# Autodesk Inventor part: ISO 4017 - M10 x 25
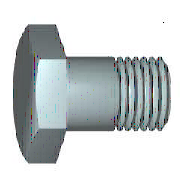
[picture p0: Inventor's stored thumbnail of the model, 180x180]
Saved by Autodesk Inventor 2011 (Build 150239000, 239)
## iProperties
IsCustomPart: 0
Created: 2009-02
Part Number: ISO 4017 - M10 x 25
Material: Stainless Steel, 440C
Description: Hexagon head screws
Document SubType Name: Modeling
Standard: ISO 4017
Designer: V.de Jong
Standard Revision: Third edition 1999-08-15
Standards Organization: ISO
Language: en-US
Size Designation: M10 x 25
Categories: <MemberInstance><Categories><Category DisplayName="Fasteners" InternalName="e4da775c-781d-43d5-af7c-5136215cf5a6" Mnemonic="FSTN"><Category DisplayName="Bolts"
Density: 7.75 g/cm^3
Mass: 25.8332 g
Surface Area: 15.4943 cm^2
Volume: 3.33332 cm^3
Author: V.de Jong
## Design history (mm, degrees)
body "Solid1"
workplane "Work Plane1"
revolve "Body" stored, may be unused: angle "d12" = 90 deg
sketch "Sketch2"
  geometry: L1 (0, 9.238)-(8, 4.619); L2 (8, 4.619)-(8, -4.619); L3 (8, -4.619)-(0, -9.238); L4 (0, -9.238)-(-8, -4.619); L5 (-8, -4.619)-(-8, 4.619); L6 (-8, 4.619)-(0, 9.238); 2 further points
  constraints: 12 end point, 1 coincident, 1 vertical, 11 other
  dimensions: "d11" = 16 distance between parallel lines of L5 L2 (= SW)
extrude "Head" join sketch "Sketch2" distance "d3" = 5.8 (= KOH - SD); taper "d4" = 0 deg
revolve "Chamfer1" stored, may be unused: angle "d21" = 90 deg
feature "Thread" dims "d15" = 20.5 (= GEL), "d16" = 0
chamfer "Chamfer2" distance "d6" = 0.92018 (= -0.5 x SPD + 0.5 x GD); stored, may be unused: second distance "d7" = 0.92028 (computed from GUL), angle "d55" = 45 deg
sketch "Sketch1"
  geometry: L1 (0, 7.315)-(0, 5); L2 (4.5, 5)-(25, 5); L3 (25, 5)-(25, 0); L4 (25, 0)-(-0.6, 0); L5 (-5.72, 0)-(30.12, 0) reference; L6 (-0.6, 0)-(-0.6, 7.315); L7 (-0.6, 7.315)-(0, 7.315); L8 (4.5, 5)-(3.58, 5); L9 (3.58, 5)-(0, 5); L10 (0, -1.463)-(0, 8.778) reference
  constraints: 16 end point, 2 collinear, 2 perpendicular, 1 parallel
  dimensions: "d0" = 25 distance between parallel lines of L3 L1 (= NLG); "d1" = 20.5 distance from line of L2.start L3 (= GEL); "d2" = 10 diameter of L2 L4 (= GD); "d9" = 0.6001 distance between parallel lines of L6 L1 (computed from SD); "d10" = 14.63 diameter of L7 L4 (= SD2); "d13" = 0.92028 distance of L2.start L8.end (computed from GAL); "d14" = 10 diameter of L9 L4 (= BDM)
sketch "Sketch4"
  geometry: L1 (-6.4, 8)-(-6.4, 9.238); L2 (-6.4, 9.238)-(-5.686, 9.238); L3 (-5.686, 9.238)-(-6.4, 8); L4 (-7.56, 0)-(0.56, 0) reference; L5 (-0.6, 9.238)-(-6.4, 9.238) reference; L6 (-6.4, 4.619)-(-6.4, 9.238) reference
  constraints: 6 end point, 2 collinear, 1 perpendicular, 1 vertical
  dimensions: "d5" = 30 deg angle of L3 L1 (= ANG1); "d19" = 16 diameter of L1.start L4 (= SW0)
other parameters: "NLG" = 25 [user parameter; used in 1 equation term], "GD" = 10 (= NND) [user parameter; used in 2 equation terms], "BDM" = 10 (= NND) [user parameter; used in 1 equation term], "KOH" = 6.4 [user parameter; used in 1 equation term], "GEL" = 20.5 [user parameter; used in 2 equation terms], "SW" = 16 [user parameter; used in 2 equation terms], "SW0" = 16 (= SW) [user parameter; used in 1 equation term], "SPD" = 8.15965 (= NND - 1.2269 x PTC) [user parameter; used in 1 equation term], "SD2" = 14.63 [user parameter; used in 2 equation terms], "SD" = 0.6 [user parameter; used in 2 equation terms], "ANG1" = 30 deg [user parameter; used in 1 equation term], "GAL" = 0.92018 (= 0.61345 x PTC) [user parameter; used in 1 equation term], "GUL" = 0.92018 (= 0.61345 x PTC) [user parameter; used in 1 equation term], "d8" = 0, "RR" = 0.4 [user parameter], "d57" = 0, "d58" = 0, "TPU" = 6.66667 (computed from PTC) [user parameter], "GD1" = 8.15965 (= THREADDIA - 1.2269 x PTC) [user parameter], "SDH" = 14.63 (= SD2) [user parameter], "SDHG" = 4.5 [user parameter], "TOA" = 30 deg [user parameter], "PTC" = 1.5 [user parameter; used in 5 equation terms], "E0" = 18.48 [user parameter]
